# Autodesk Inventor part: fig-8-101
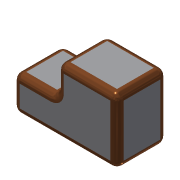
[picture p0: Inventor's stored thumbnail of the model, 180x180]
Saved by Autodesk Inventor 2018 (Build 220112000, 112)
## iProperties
Shininess: 64.0
Length Units: 11269
Angle Units: 11279
Time Units: 11290
Mass Units: 11283
Length Display Precision: 3
Angle Display Precision: 2
Compacted: True
Part Number: fig-8-101
Document SubType Name: Modeling
Created: 2002-12
Designer: deepak
Density: 1 g/cm^3
Material: Generic
Appearance: Default
Density: 0.0
Volumn: 0.0
Area: 0.0
PropertySet Name: Model Information
Control State: 0
Master: False
Checked Out: False
Author: deepak
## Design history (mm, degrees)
sketch "Sketch1"
  geometry: L1 (-26.972, 23.346)-(8.906, 23.346); L2 (8.906, 23.346)-(8.906, 5.025); L3 (8.906, -15.84)-(-26.972, -15.84); L4 (-26.972, -15.84)-(-26.972, 23.346); L5 (8.906, -15.84)-(35.369, -15.84); L6 (35.369, -15.84)-(35.369, 5.025); L7 (35.369, 5.025)-(8.906, 5.025)
  constraints: 14 end point, 3 parallel, 2 horizontal, 2 perpendicular
extrude "Extrusion1" new body sketch "Sketch1" stored distance "d0" = 30; taper "d1" = 0 deg
fillet "Fillet1" dims "d2" = 4, "d3" = 4
body "Solid1"
